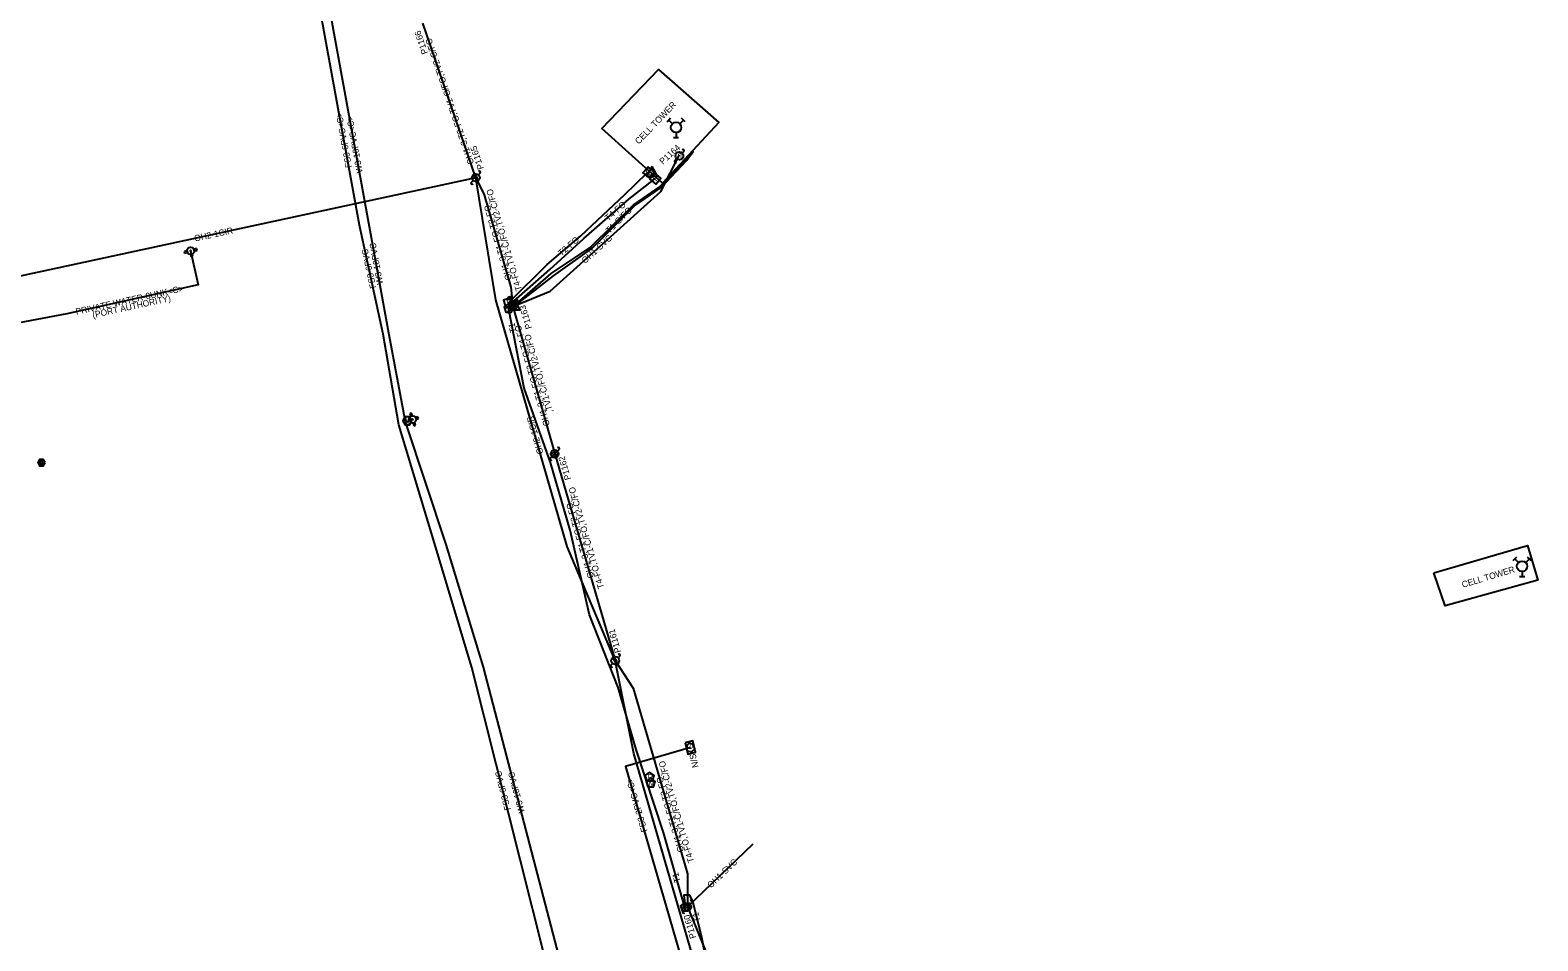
# Model space of a CAD drawing. Extents: x 2336688 to 2352634, y 362473 to 369571.
# Drawn here: x 2346202 to 2347159, y 368069 to 368647 of the extents above; entities that cross this region are included whole.
import ezdxf

# ---------------------------------------------------------------- set-up
doc = ezdxf.new("R2010")
doc.units = 0
for name, color, linetype in [('RD_EX_DV_TX_Prop', 7, 'Continuous'), ('RD_EX_RW', 7, 'Continuous'), ('RD_EX_RW_TX', 7, 'Continuous'), ('RD_HC_Data_Tic', 7, 'Continuous'), ('RD_PD_CstnLmt', 7, 'Continuous'), ('RD_PD_PatLn3', 7, 'Continuous'), ('RD_PD_PatLn4', 7, 'Continuous'), ('RD_SHT_ShtClip', 7, 'Continuous'), ('RD_Sketch1', 7, 'Continuous'), ('RD_Sketch2', 7, 'Continuous'), ('RD_Sketch5', 7, 'Continuous')]:
    doc.layers.add(name, color=color, linetype=linetype)

# ---------------------------------------------------------------- blocks, each defined once
blk = doc.blocks.new('GW')
at = {"layer": 'RD_HC_Data_Tic'}
blk.add_line((0, 0), (0, 5), dxfattribs=at)
blk.add_circle((0, 0), 2, dxfattribs=at)

msp = doc.modelspace()

# ---------------------------------------------------------------- linework, layer by layer
at = {"layer": 'RD_EX_RW_TX'}
for p, q in [((2346607, 368590.34), (2346605.83, 368589.17)), ((2346608.17, 368591.5), (2346607, 368590.34)), ((2346609.33, 368588), (2346607, 368590.34)), ((2346616.33, 368590.34), (2346614, 368588)), ((2346616.33, 368590.34), (2346615.17, 368591.5)), ((2346617.5, 368589.17), (2346616.33, 368590.34)), ((2346611.67, 368579.06), (2346610.02, 368579.06)), ((2346611.67, 368582.37), (2346611.67, 368579.06)), ((2346613.32, 368579.06), (2346611.67, 368579.06)), ((2347144.23, 368311.66), (2347143.06, 368310.49)), ((2347145.4, 368312.83), (2347144.23, 368311.66)), ((2347146.57, 368309.33), (2347144.23, 368311.66)), ((2347153.57, 368311.66), (2347151.23, 368309.33)), ((2347153.57, 368311.66), (2347152.4, 368312.83)), ((2347154.73, 368310.49), (2347153.57, 368311.66)), ((2347148.9, 368303.69), (2347148.9, 368300.38)), ((2347148.9, 368300.38), (2347147.25, 368300.38)), ((2347150.55, 368300.38), (2347148.9, 368300.38))]:
    msp.add_line(p, q, dxfattribs=at)
for points in [[(2346564.51, 368584.99), (2346600.46, 368622.46), (2346638.82, 368588.72), (2346603.07, 368550.32)], [(2346593.85, 368560.6), (2346590.66, 368556.75), (2346594.52, 368553.56), (2346597.7, 368557.42)], [(2346598.11, 368556.63), (2346594.93, 368552.77), (2346598.79, 368549.59), (2346601.97, 368553.44)], [(2346506.9, 368477.41), (2346502.12, 368475.95), (2346503.57, 368471.17), (2346508.35, 368472.62)], [(2346505.39, 368473.79), (2346502.53, 368471.71), (2346503.62, 368468.36), (2346507.15, 368468.36), (2346508.24, 368471.71)], [(2347092.94, 368302.9), (2347152.3, 368320.18), (2347158.89, 368298.14), (2347100.05, 368281.92)], [(2346617.32, 368093.59), (2346614.47, 368091.52), (2346615.56, 368088.16), (2346619.08, 368088.16), (2346620.17, 368091.52)]]:
    msp.add_lwpolyline(points, close=True, dxfattribs=at)
for points in [[(2346634.25, 368040.04), (2346627.73, 368072.39), (2346622.22, 368094.23), (2346620.46, 368098.27), (2346616.56, 368098.21), (2346617.48, 368091.32), (2346617.32, 368090.59), (2346617.12, 368091.19), (2346603.61, 368137.99), (2346586.43, 368190.78), (2346574.8, 368230.13), (2346556.77, 368276.23), (2346544.47, 368329.97), (2346532.03, 368372.96), (2346515.15, 368420.17), (2346505.46, 368470), (2346505.39, 368470.79), (2346506.42, 368469.99), (2346533.92, 368491.4), (2346558.12, 368508.78), (2346585.2, 368535.92), (2346602.14, 368547.48), (2346618.51, 368564.91), (2346622.61, 368570.42), (2346621.88, 368570.89)], [(2346621.22, 368570.6), (2346621.59, 368569.97), (2346617.9, 368565.58), (2346601.42, 368548.19), (2346584.8, 368536.74), (2346557.54, 368509.79), (2346532.24, 368492.96), (2346508.77, 368472.52), (2346508.09, 368472.04)], [(2346508.09, 368472.04), (2346505.23, 368474.29), (2346506.34, 368475.25), (2346529.81, 368498.6), (2346551.25, 368516.88), (2346579.17, 368542.98), (2346593.06, 368556.56), (2346594.18, 368557.08)], [(2346508.09, 368472.04), (2346506.76, 368473.54), (2346531.47, 368495.38), (2346553.1, 368515.16), (2346581.78, 368540.07), (2346597.07, 368552.18), (2346598.45, 368553.11)]]:
    msp.add_lwpolyline(points, dxfattribs=at)
for centre in [(2346611.67, 368585.67), (2347148.9, 368306.99)]:
    msp.add_circle(centre, 3.3, dxfattribs=at)
at = {"layer": 'RD_HC_Data_Tic'}
for p, q in [((2346615.53, 368569.31), (2346616.59, 368570.37)), ((2346610.94, 368564.71), (2346612, 368565.77)), ((2346481.67, 368550.89), (2346482.73, 368551.95)), ((2346486.27, 368555.49), (2346487.33, 368556.55)), ((2346505.68, 368471.39), (2346508.74, 368474.46)), ((2346506.33, 368470.27), (2346509.86, 368473.81)), ((2346509.86, 368473.81), (2346510.92, 368474.87)), ((2346505.27, 368469.21), (2346506.33, 368470.27)), ((2346507.45, 368469.63), (2346510.51, 368472.69)), ((2346532.18, 368377.75), (2346535.24, 368380.81)), ((2346532.82, 368376.63), (2346536.36, 368380.17)), ((2346533.94, 368375.98), (2346537.01, 368379.05)), ((2346536.36, 368380.17), (2346537.42, 368381.23)), ((2346531.76, 368375.57), (2346532.82, 368376.63)), ((2346570.21, 368244.32), (2346571.27, 368245.38)), ((2346574.8, 368248.91), (2346575.86, 368249.97)), ((2346616.43, 368090.15), (2346619.49, 368093.21)), ((2346617.07, 368089.03), (2346620.61, 368092.57)), ((2346618.19, 368088.38), (2346621.26, 368091.45)), ((2346620.61, 368092.57), (2346621.67, 368093.63)), ((2346616.01, 368087.97), (2346617.07, 368089.03))]:
    msp.add_line(p, q, dxfattribs=at)
for points in [[(2346484.11, 368555.73), (2346484.93, 368553.72), (2346483.47, 368554.52), (2346485.35, 368551.84), (2346485.35, 368551.84), (2346484.15, 368553.93), (2346485.53, 368553.13)], [(2346572.64, 368249.15), (2346573.47, 368247.14), (2346572.01, 368247.94), (2346573.89, 368245.26), (2346573.89, 368245.26), (2346572.68, 368247.36), (2346574.07, 368246.55)]]:
    msp.add_lwpolyline(points, close=True, dxfattribs=at)
for centre in [(2346613.77, 368567.54), (2346484.5, 368553.72), (2346508.09, 368472.04), (2346534.59, 368378.4), (2346573.04, 368247.14), (2346618.84, 368090.8)]:
    msp.add_circle(centre, 2.5, dxfattribs=at)
for centre, start, end in [((2346616.06, 368570.9), 315, 135), ((2346611.47, 368564.18), 135, 315), ((2346482.2, 368550.36), 135, 315), ((2346486.8, 368557.08), 315, 135), ((2346510.39, 368475.4), 315, 135), ((2346505.8, 368468.68), 135, 315), ((2346536.89, 368381.76), 315, 135), ((2346532.29, 368375.04), 135, 315), ((2346570.74, 368243.79), 135, 315), ((2346575.33, 368250.5), 315, 135), ((2346621.14, 368094.16), 315, 135), ((2346616.54, 368087.44), 135, 315)]:
    msp.add_arc(centre, 0.75, start, end, dxfattribs=at)
at = {"layer": 'RD_PD_PatLn3'}
for points in [[(2346596.39, 368560.72), (2346592.93, 368554.72), (2346599.86, 368554.72)], [(2346509.28, 368475.89), (2346505.81, 368469.89), (2346512.74, 368469.89)]]:
    msp.add_lwpolyline(points, close=True, dxfattribs=at)
at = {"layer": 'RD_SHT_ShtClip'}
for p, q in [((2346484.5, 368553.72), (2346450.91, 368651.81)), ((2346508.09, 368472.04), (2346534.59, 368378.4)), ((2346534.59, 368378.4), (2346573.04, 368247.14)), ((2346618.84, 368090.8), (2346660.67, 368130.85))]:
    msp.add_line(p, q, dxfattribs=at)
for points in [[(2346508.09, 368472.04), (2346531.72, 368481.57), (2346601.91, 368545), (2346613.81, 368568.21)], [(2346484.5, 368553.72), (2346106.63, 368472.05), (2345728.21, 368390.74), (2345709.42, 368405.61), (2345692.18, 368485.98)], [(2346573.04, 368247.14), (2346542.54, 368319.5), (2346497.27, 368476.25), (2346484.5, 368553.72)], [(2346484.5, 368553.72), (2346489.74, 368542.74), (2346506.68, 368484.12), (2346508.09, 368472.04)], [(2346659.61, 367949.85), (2346637.77, 368005.99), (2346584.75, 368188.07), (2346573.04, 368247.14)], [(2346573.04, 368247.14), (2346584.39, 368229.63), (2346618.95, 368111.67), (2346618.84, 368090.8)], [(2346618.84, 368090.8), (2346634.17, 368053.59), (2346652.7, 367989.5), (2346659.61, 367949.85)]]:
    msp.add_lwpolyline(points, dxfattribs=at)
at = {"layer": 'RD_Sketch2'}
for p, q in [((2346301.13, 368507.29), (2346299.36, 368506.88)), ((2346299.36, 368506.88), (2346299.62, 368505.76)), ((2346299.62, 368505.76), (2346301.44, 368506.18)), ((2346303.33, 368505.02), (2346303.67, 368503.56)), ((2346303.67, 368503.56), (2346304.8, 368503.82)), ((2346304.8, 368503.82), (2346304.47, 368505.25)), ((2346307.24, 368508.71), (2346305.53, 368508.32)), ((2346305.75, 368507.18), (2346307.5, 368507.59)), ((2346307.5, 368507.59), (2346307.24, 368508.71)), ((2346443.76, 368404.26), (2346442.66, 368403.9)), ((2346442.66, 368403.9), (2346443.21, 368402.23)), ((2346444.32, 368402.56), (2346443.76, 368404.26)), ((2346444.63, 368397.95), (2346445.2, 368396.22)), ((2346445.2, 368396.22), (2346446.29, 368396.59)), ((2346446.29, 368396.59), (2346445.71, 368398.35)), ((2346447.75, 368401.91), (2346446.36, 368401.45)), ((2346446.69, 368400.35), (2346448.12, 368400.82)), ((2346448.12, 368400.82), (2346447.75, 368401.91))]:
    msp.add_line(p, q, dxfattribs=at)
for points in [[(2346416.61, 368524.92), (2346351.49, 368881.57), (2346222.86, 368977.1)], [(2346741.1, 367241.32), (2346737.67, 367252.1), (2346741.22, 367257.03), (2346757.99, 367295.14), (2346748.08, 367346.19), (2346732.63, 367400.55), (2346721.55, 367441.12), (2346697.44, 367518.56), (2346693, 367533.8), (2346684.39, 367569.05), (2346661.25, 367635.9), (2346649.68, 367679.89), (2346635.8, 367728.93), (2346621.54, 367774.47), (2346588.43, 367887.35), (2346563.64, 367964.78), (2346538.6, 368055.07), (2346489.45, 368242.94), (2346465.74, 368320.9), (2346439.88, 368398.73), (2346429.38, 368455.01), (2346416.61, 368524.92)], [(2346303.44, 368507.32), (2346308.19, 368485.62), (2346224.86, 368467.37), (2346190.1, 368460.68), (2345819.16, 368376.8), (2345758.74, 368364.41), (2345705.06, 368353.9), (2345620.96, 368334.75)], [(2346439.88, 368398.73), (2346443.14, 368399.77), (2346444.39, 368400.25)]]:
    msp.add_lwpolyline(points, dxfattribs=at)
for points in [[(2346443.89, 368399.39), (2346442.45, 368401.89), (2346439.56, 368401.89), (2346438.12, 368399.39), (2346439.56, 368396.89), (2346442.45, 368396.89)], [(2346594.81, 368176.23), (2346591.91, 368174.12), (2346593.02, 368170.71), (2346596.6, 368170.71), (2346597.71, 368174.12)], [(2346595.59, 368172.45), (2346592.69, 368170.34), (2346593.8, 368166.93), (2346597.38, 368166.93), (2346598.49, 368170.34)]]:
    msp.add_lwpolyline(points, close=True, dxfattribs=at)
for centre, radius in [((2346303.44, 368507.32), 2.31), ((2346303.44, 368507.32), 0.289), ((2346444.39, 368400.25), 2.31), ((2346444.39, 368400.25), 0.289)]:
    msp.add_circle(centre, radius, dxfattribs=at)
for centre, start, end in [((2346303.44, 368507.32), 180.79017, 209.76649), ((2346303.44, 368507.32), 267.35072, 296.31795), ((2346303.44, 368507.32), 356.44389, 25.42021), ((2346444.39, 368400.25), 91.60125, 120.57757), ((2346444.39, 368400.25), 275.94754, 304.92386), ((2346444.39, 368400.25), 2.50808, 31.47532)]:
    msp.add_arc(centre, 2.31, start, end, dxfattribs=at)
at = {"layer": 'RD_Sketch5'}
for points in [[(2346410.56, 368523.52), (2346345.82, 368878.04), (2346219.16, 368972.12)], [(2346598.4, 367625.28), (2346629.76, 367632.55), (2346647.94, 367636.93), (2346638.63, 367677.9), (2346626.35, 367726.44), (2346612.03, 367770.42), (2346577.43, 367886.9), (2346552.76, 367966.42), (2346528.36, 368058.69), (2346481.97, 368242.83), (2346458.89, 368319.64), (2346435.71, 368396.9), (2346425.78, 368454.45), (2346410.56, 368523.52)], [(2346620.75, 368191.93), (2346579.58, 368179.97), (2346833.73, 367304.59), (2346858.75, 367292.23), (2346857.22, 367289.15)]]:
    msp.add_lwpolyline(points, dxfattribs=at)
for points in [[(2346210.99, 368372.81), (2346209.84, 368374.81), (2346207.53, 368374.81), (2346206.38, 368372.81), (2346207.53, 368370.82), (2346209.84, 368370.82)], [(2346209.5, 368373.63), (2346207.87, 368373.63), (2346207.87, 368372), (2346209.5, 368372)], [(2346617.45, 368194.96), (2346619.19, 368187.72), (2346624.05, 368188.89), (2346622.31, 368196.13)], [(2346620.08, 368194.74), (2346617.98, 368192.75), (2346618.66, 368189.94), (2346621.43, 368189.12), (2346623.52, 368191.11), (2346622.84, 368193.92)]]:
    msp.add_lwpolyline(points, close=True, dxfattribs=at)

# ---------------------------------------------------------------- block references
at = {"layer": 'RD_HC_Data_Tic', "xscale": 0.5546771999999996, "yscale": 0.5546771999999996, "rotation": -159.1938379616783}
msp.add_blockref('GW', (2346506.25, 368477.23), dxfattribs=at)

# ---------------------------------------------------------------- texts
at = {"layer": 'RD_EX_DV_TX_Prop'}
for s, rotation, p in [('P1166', 108.90593, (2346454.21, 368632.88)), ('P1165', 108.90593, (2346489.7, 368559.69)), ('P1164', 42.10565, (2346603.27, 368561.86)), ('P1163', 106.32531, (2346520.27, 368458.28)), ('P1162', 106.32531, (2346545.05, 368362.42)), ('P1161', 106.32935, (2346576.82, 368252.68)), ('P1160', 106.13126, (2346624.47, 368071.27))]:
    msp.add_text(s, height=4, rotation=rotation, dxfattribs=at).set_placement(p)
at = {"layer": 'RD_EX_RW'}
for s, rotation, p in [('CELL TOWER', 46.18403, (2346588.02, 368574.64)), ('T4-FO', 40.97237, (2346568.58, 368525.96)), ('T1-C/FO', 45.06553, (2346569.39, 368517.99)), ('T2-FO', 40.44976, (2346538.8, 368503.64)), ('T1', 101.00819, (2346510.29, 368455.63)), ('CELL TOWER', 16.72634, (2347111.28, 368293.3)), ('T1', 106.09938, (2346614.67, 368106.88)), ('T1', 104.1559, (2346627.3, 368081.68))]:
    msp.add_text(s, height=4, rotation=rotation, dxfattribs=at).set_placement(p)
at = {"layer": 'RD_EX_RW_TX'}
for rotation, p in [(50.44298, (2346595, 368554.93)), (50.44298, (2346599.27, 368550.96)), (16.91754, (2346504.73, 368472.04))]:
    msp.add_text('F', height=4, rotation=rotation, dxfattribs=at).set_placement(p)
for p in [(2346504.16, 368468.56), (2346616.09, 368088.36)]:
    msp.add_text('T', height=3.75, dxfattribs=at).set_placement(p)
at = {"layer": 'RD_HC_Data_Tic'}
msp.add_text('m', height=4, rotation=360, dxfattribs=at).set_placement((2346612.58, 368566.21))
at = {"layer": 'RD_PD_CstnLmt'}
for s, rotation, p in [('W3-10PVC<C>', 100.34783, (2346412.78, 368557.02)), ('W3-10PVC', 100.34783, (2346425.7, 368486.27)), ('PRIVATE WATER-8UNK<C>', 12.35721, (2346230.89, 368466.64)), ('(PORT AUTHORITY)', 12.35721, (2346241.48, 368464.56)), ('W3-10PVC', 104.66199, (2346515.59, 368150.93))]:
    msp.add_text(s, height=4, rotation=rotation, dxfattribs=at).set_placement(p)
at = {"layer": 'RD_PD_PatLn3'}
for p in [(2346595.64, 368555.52), (2346508.52, 368470.69)]:
    msp.add_text('U', height=2.4, dxfattribs=at).set_placement(p)
at = {"layer": 'RD_PD_PatLn4'}
for s, rotation, p in [('OH1-3,T2-FO,TV1-C/FO,TV2-C/FO', 108.90593, (2346483.47, 368562.91)), ('T4-FO,TV1-C/FO,TV2-C/FO', 106.32935, (2346513.84, 368482.5)), ('OH1-3,T1-FO,T2-FO,', 106.32935, (2346507.39, 368489.22)), ('OH2-1CIR', 12.19515, (2346306.19, 368513.14)), ('OH1-SVC', 42.10565, (2346553.87, 368498.89)), ('OH1-3,T1-FO,T2-FO,T4-FO', 106.32935, (2346531.59, 368396.63)), (',TV1-C/FO,TV2-C/FO', 106.32935, (2346533.58, 368405.12)), ('OH2-1CIR', 106.108, (2346527.5, 368378.8)), ('OH1-3,T1-FO,T2-FO,', 106.32935, (2346559.62, 368300.08)), ('T4-FO,TV1-C/FO,TV2-C/FO', 106.32935, (2346566.07, 368293.35)), ('T4-FO,TV1-C/FO,TV2-C/FO', 106.32935, (2346623.24, 368119.42)), ('OH1-3,T1-FO,T2-FO,', 106.32935, (2346616.79, 368126.14)), ('OH1-SVC', 43.75821, (2346633.79, 368102.34))]:
    msp.add_text(s, height=4, rotation=rotation, dxfattribs=at).set_placement(p)
at = {"layer": 'RD_Sketch1'}
for s, rotation, p in [('FS3-6PVC<C>', 100.34783, (2346405.85, 368560.41)), ('FS3-6PVC', 102.42468, (2346421.34, 368483.88)), ('N/S', 103.51761, (2346626.03, 368179.65)), ('FS3-6PVC', 104.14111, (2346506.76, 368152.62)), ('FS3-2PVC<C>', 106.18951, (2346593.57, 368138.94))]:
    msp.add_text(s, height=4, rotation=rotation, dxfattribs=at).set_placement(p)
at = {"layer": 'RD_Sketch2'}
for s, p in [('V', (2346439.8, 368397.51)), ('M', (2346594.22, 368167.4))]:
    msp.add_text(s, height=3.75, dxfattribs=at).set_placement(p)
msp.add_text('P', height=3.75, rotation=360, dxfattribs=at).set_placement((2346593.66, 368171.3))
at = {"layer": 'RD_Sketch5'}
msp.add_text('G', height=3.53, rotation=103.51761, dxfattribs=at).set_placement((2346622.72, 368191.29))

doc.saveas('drawing.dxf')
